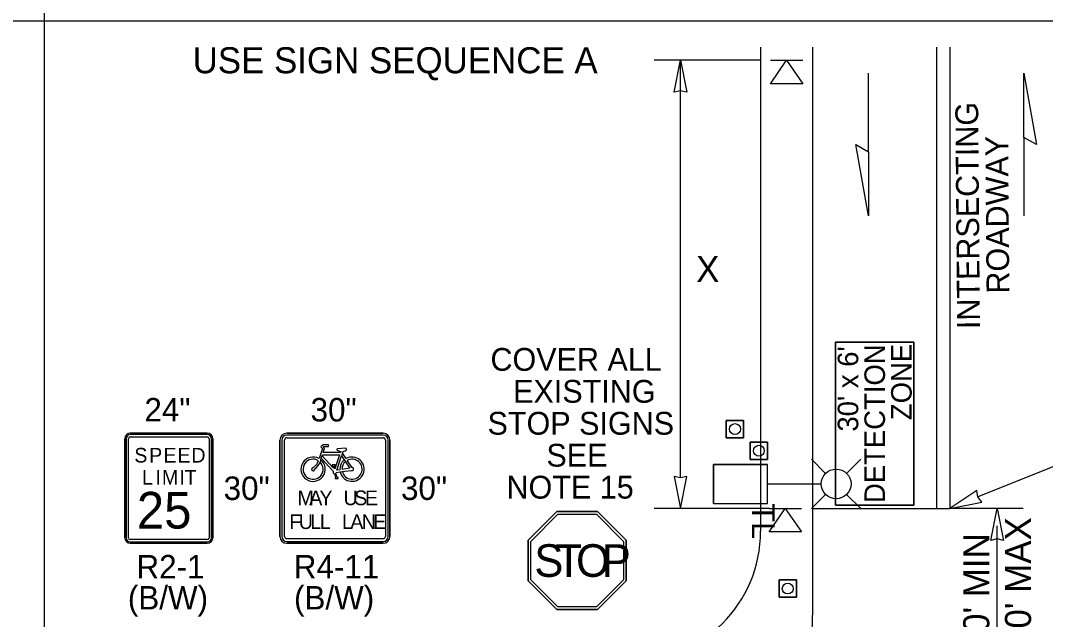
# Model space of a CAD drawing. Extents: x 99979.8 to 100075.7, y 99995 to 100010.7.
# Drawn here: x 100045.178 to 100048.321, y 100004.285 to 100006.122 of the extents above; entities that cross this region are included whole.
import ezdxf

# ---------------------------------------------------------------- set-up
doc = ezdxf.new("R2010")
doc.units = 0
for name, color, linetype in [('RD_ED_ShoulderPavedEdge', 7, 'Continuous'), ('RD_MK_LineDblYellowCenter', 7, 'Continuous'), ('RD_MK_LineEdgeWhite', 7, 'Continuous'), ('RD_MK_LineEdgeWhiteNew', 7, 'Continuous'), ('RD_MK_LineStop', 7, 'Continuous'), ('SH_DE_DetailBody1Text', 7, 'Continuous'), ('TR_SN_ConstructionSigns', 7, 'Continuous'), ('TR_WZ_PortableLightStandard', 7, 'Continuous'), ('TR_WZ_PortableSignMountBlk-Org', 7, 'Continuous'), ('TR_WZ_PortableSignMountBlk-Wht', 7, 'Continuous'), ('TR_WZ_TrafficCone', 7, 'Continuous'), ('TR_WZ_WorkZoneDetails', 7, 'Continuous'), ('TR_WZ_WorkZoneTextCurrent', 7, 'Continuous')]:
    doc.layers.add(name, color=color, linetype=linetype)

msp = doc.modelspace()

# ---------------------------------------------------------------- linework, layer by layer
at = {"layer": 'RD_ED_ShoulderPavedEdge'}
msp.add_lwpolyline([(100047.4475, 100006.0405), (100047.4475, 100004.5559)], dxfattribs=at)
msp.add_arc((100047.0475, 100004.5559), 0.4, 270, 0, dxfattribs=at)
at = {"layer": 'RD_MK_LineDblYellowCenter'}
for p, q in [((100047.9875, 100006.0405), (100047.9875, 100004.6259)), ((100048.0275, 100006.0405), (100048.0275, 100004.6259))]:
    msp.add_line(p, q, dxfattribs=at)
at = {"layer": 'RD_MK_LineEdgeWhite'}
for p, q in [((100047.6075, 100004.5559), (100047.6075, 100006.0405)), ((100047.6075, 100004.3159), (100047.6075, 100004.5559))]:
    msp.add_line(p, q, dxfattribs=at)
at = {"layer": 'RD_MK_LineEdgeWhiteNew'}
msp.add_arc((100046.1076, 100004.3239), 1.5, 277.2601, 359.6954, dxfattribs=at)
at = {"layer": 'RD_MK_LineStop'}
msp.add_line((100047.6075, 100004.6259), (100048.0275, 100004.6259), dxfattribs=at)
at = {"layer": 'TR_SN_ConstructionSigns'}
for p, q in [((100045.5142, 100004.8565), (100045.7505, 100004.8565)), ((100045.7505, 100004.8565), (100045.5142, 100004.8565)), ((100045.7505, 100004.8565), (100045.5142, 100004.8565)), ((100045.9944, 100004.8565), (100046.2897, 100004.8565)), ((100046.2897, 100004.8565), (100045.9944, 100004.8565)), ((100046.2897, 100004.8565), (100045.9944, 100004.8565)), ((100045.4973, 100004.5358), (100045.4973, 100004.8396)), ((100045.4973, 100004.8396), (100045.4973, 100004.5358)), ((100045.4973, 100004.8396), (100045.4973, 100004.5358)), ((100045.5016, 100004.8396), (100045.5016, 100004.5358)), ((100045.5086, 100004.5358), (100045.5086, 100004.8396)), ((100045.7505, 100004.8523), (100045.5142, 100004.8523)), ((100045.5142, 100004.8452), (100045.7505, 100004.8452)), ((100045.7561, 100004.8396), (100045.7561, 100004.5358)), ((100045.7631, 100004.5358), (100045.7631, 100004.8396)), ((100045.7673, 100004.8396), (100045.7673, 100004.5358)), ((100045.7673, 100004.5358), (100045.7673, 100004.8396)), ((100045.7673, 100004.5358), (100045.7673, 100004.8396)), ((100045.9733, 100004.5401), (100045.9733, 100004.8354)), ((100045.9733, 100004.8354), (100045.9733, 100004.5401)), ((100045.9733, 100004.8354), (100045.9733, 100004.5401)), ((100045.9789, 100004.8354), (100045.9789, 100004.5401)), ((100045.9873, 100004.5401), (100045.9873, 100004.8354)), ((100046.2897, 100004.8508), (100045.9944, 100004.8508)), ((100045.9944, 100004.8424), (100046.2897, 100004.8424)), ((100046.2967, 100004.8354), (100046.2967, 100004.5401)), ((100046.3051, 100004.5401), (100046.3051, 100004.8354)), ((100046.3108, 100004.8354), (100046.3108, 100004.5401)), ((100046.3108, 100004.5401), (100046.3108, 100004.8354)), ((100046.3108, 100004.5401), (100046.3108, 100004.8354)), ((100046.1037, 100004.8097), (100046.0933, 100004.7786)), ((100046.106, 100004.8213), (100046.0991, 100004.8143)), ((100046.0991, 100004.8143), (100046.1037, 100004.8097)), ((100046.1059, 100004.7972), (100046.1101, 100004.8097)), ((100046.1586, 100004.7972), (100046.1059, 100004.7972)), ((100046.1225, 100004.8213), (100046.106, 100004.8213)), ((100046.1061, 100004.8137), (100046.1083, 100004.8158)), ((100046.1101, 100004.8097), (100046.1061, 100004.8137)), ((100046.1083, 100004.8158), (100046.1225, 100004.8158)), ((100046.1225, 100004.8158), (100046.1225, 100004.8213)), ((100046.1744, 100004.8101), (100046.1495, 100004.8084)), ((100046.1597, 100004.8006), (100046.1586, 100004.7972)), ((100046.1647, 100004.7949), (100046.1621, 100004.787)), ((100046.1647, 100004.7949), (100046.1667, 100004.8007)), ((100046.1759, 100004.7784), (100046.1647, 100004.7949)), ((100046.0985, 100004.775), (100046.0963, 100004.7682)), ((100046.0985, 100004.775), (100046.1001, 100004.7797)), ((100046.1001, 100004.7797), (100046.1025, 100004.7868)), ((100046.1001, 100004.7797), (100046.1367, 100004.7399)), ((100046.1025, 100004.7868), (100046.1037, 100004.7906)), ((100046.1371, 100004.7492), (100046.1025, 100004.7868)), ((100046.1037, 100004.7906), (100046.1564, 100004.7906)), ((100046.1564, 100004.7906), (100046.1419, 100004.7473)), ((100046.1474, 100004.7428), (100046.1621, 100004.787)), ((100046.1621, 100004.787), (100046.1705, 100004.7746)), ((100046.1705, 100004.7746), (100046.1742, 100004.7691)), ((100046.1742, 100004.7691), (100046.188, 100004.7488)), ((100046.1945, 100004.751), (100046.1796, 100004.7729)), ((100046.1424, 100004.7599), (100046.1336, 100004.7599)), ((100046.1358, 100004.7566), (100046.1371, 100004.7492)), ((100046.1419, 100004.7473), (100046.1402, 100004.7566)), ((100046.1402, 100004.7566), (100046.1424, 100004.7566)), ((100046.141, 100004.7318), (100046.1446, 100004.721)), ((100046.1424, 100004.7566), (100046.1424, 100004.7599)), ((100046.1493, 100004.721), (100046.1452, 100004.7332)), ((100046.1469, 100004.7361), (100046.1582, 100004.7377)), ((100046.1573, 100004.7442), (100046.1474, 100004.7428)), ((100046.1582, 100004.7377), (100046.1647, 100004.7387)), ((100046.188, 100004.7488), (100046.1638, 100004.7452)), ((100046.1647, 100004.7387), (100046.191, 100004.7426)), ((100046.1446, 100004.721), (100046.1428, 100004.721)), ((100046.1428, 100004.721), (100046.1428, 100004.7177)), ((100046.1428, 100004.7177), (100046.1516, 100004.7177)), ((100046.1516, 100004.721), (100046.1493, 100004.721)), ((100046.1516, 100004.7177), (100046.1516, 100004.721)), ((100046.8229, 100004.6159), (100046.735, 100004.528)), ((100046.8229, 100004.6159), (100046.735, 100004.528)), ((100046.7428, 100004.5248), (100046.8261, 100004.6081)), ((100046.9472, 100004.6159), (100046.8229, 100004.6159)), ((100046.9472, 100004.6159), (100046.8229, 100004.6159)), ((100046.8261, 100004.6081), (100046.9439, 100004.6081)), ((100046.9439, 100004.6081), (100047.0272, 100004.5248)), ((100047.035, 100004.528), (100046.9472, 100004.6159)), ((100047.035, 100004.528), (100046.9472, 100004.6159)), ((100045.7505, 100004.5302), (100045.5142, 100004.5302)), ((100045.5142, 100004.5232), (100045.7505, 100004.5232)), ((100045.7505, 100004.519), (100045.5142, 100004.519)), ((100045.5142, 100004.519), (100045.7505, 100004.519)), ((100045.5142, 100004.519), (100045.7505, 100004.519)), ((100046.2897, 100004.533), (100045.9944, 100004.533)), ((100045.9944, 100004.5246), (100046.2897, 100004.5246)), ((100046.2897, 100004.519), (100045.9944, 100004.519)), ((100045.9944, 100004.519), (100046.2897, 100004.519)), ((100045.9944, 100004.519), (100046.2897, 100004.519)), ((100046.735, 100004.528), (100046.735, 100004.4038)), ((100046.735, 100004.528), (100046.735, 100004.4038)), ((100046.7428, 100004.407), (100046.7428, 100004.5248)), ((100047.0272, 100004.5248), (100047.0272, 100004.407)), ((100047.035, 100004.4038), (100047.035, 100004.528)), ((100047.035, 100004.4038), (100047.035, 100004.528)), ((100046.735, 100004.4038), (100046.8229, 100004.3159)), ((100046.735, 100004.4038), (100046.8229, 100004.3159)), ((100046.8261, 100004.3237), (100046.7428, 100004.407)), ((100047.0272, 100004.407), (100046.9439, 100004.3237)), ((100046.9472, 100004.3159), (100047.035, 100004.4038)), ((100046.9472, 100004.3159), (100047.035, 100004.4038)), ((100046.9439, 100004.3237), (100046.8261, 100004.3237)), ((100046.8229, 100004.3159), (100046.9472, 100004.3159)), ((100046.8229, 100004.3159), (100046.9472, 100004.3159))]:
    msp.add_line(p, q, dxfattribs=at)
for points in [[(100046.1336, 100004.7599), (100046.1336, 100004.7566), (100046.1358, 100004.7566)], [(100046.8229, 100004.6159), (100046.9472, 100004.6159), (100047.035, 100004.528), (100047.035, 100004.4038), (100046.9472, 100004.3159), (100046.8229, 100004.3159), (100046.735, 100004.4038), (100046.735, 100004.528), (100046.8229, 100004.6159)]]:
    msp.add_lwpolyline(points, dxfattribs=at)
for centre, radius, start, end in [((100045.5142, 100004.8396), 0.0169, 90, 180), ((100045.5142, 100004.8396), 0.0169, 90, 180), ((100045.5142, 100004.8396), 0.0169, 90, 180), ((100045.7505, 100004.8396), 0.0169, 0, 90), ((100045.7505, 100004.8396), 0.0169, 0, 90), ((100045.7505, 100004.8396), 0.0169, 0, 90), ((100045.9944, 100004.8354), 0.0211, 90, 180), ((100045.9944, 100004.8354), 0.0211, 90, 180), ((100045.9944, 100004.8354), 0.0211, 90, 180), ((100046.2897, 100004.8354), 0.0211, 0, 90), ((100046.2897, 100004.8354), 0.0211, 0, 90), ((100046.2897, 100004.8354), 0.0211, 0, 90), ((100045.5142, 100004.8396), 0.0127, 90, 180), ((100045.5142, 100004.8396), 0.00562, 90, 180), ((100045.7505, 100004.8396), 0.0127, 0, 90), ((100045.7505, 100004.8396), 0.00562, 0, 90), ((100045.9944, 100004.8354), 0.0155, 90, 180), ((100045.9944, 100004.8354), 0.00703, 90, 180), ((100046.2897, 100004.8354), 0.0155, 0, 90), ((100046.2897, 100004.8354), 0.00703, 0, 90), ((100046.1495, 100004.8062), 0.00219, 89.3854, 243.6828), ((100046.1747, 100004.8068), 0.00329, 294.5519, 96.4128), ((100046.075, 100004.7461), 0.0373, 60.5529, 50.868), ((100046.075, 100004.7461), 0.0307, 58.1532, 46.1649), ((100046.1945, 100004.7461), 0.0373, 130.0889, 182.8379), ((100046.1945, 100004.7461), 0.0373, 192.9622, 119.9648), ((100046.1945, 100004.7461), 0.0307, 131.3616, 181.6359), ((100046.1945, 100004.7461), 0.0307, 193.937, 119.0598), ((100046.075, 100004.7461), 0.00493, 105.257, 14.3233), ((100046.1415, 100004.7373), 0.00548, 151.1744, 264.8566), ((100046.1415, 100004.7373), 0.00548, 312.0053, 347.2932), ((100046.1945, 100004.7461), 0.00493, 225.1095, 90.4672), ((100045.5142, 100004.5358), 0.0169, 180, 270), ((100045.5142, 100004.5358), 0.0169, 180, 270), ((100045.5142, 100004.5358), 0.0169, 180, 270), ((100045.5142, 100004.5358), 0.0127, 180, 270), ((100045.5142, 100004.5358), 0.00562, 180, 270), ((100045.7505, 100004.5358), 0.0169, 270, 0), ((100045.7505, 100004.5358), 0.0169, 270, 0), ((100045.7505, 100004.5358), 0.0127, 270, 0), ((100045.7505, 100004.5358), 0.00562, 270, 0), ((100045.7505, 100004.5358), 0.0169, 270, 0), ((100045.9944, 100004.5401), 0.0211, 180, 270), ((100045.9944, 100004.5401), 0.0211, 180, 270), ((100045.9944, 100004.5401), 0.0211, 180, 270), ((100045.9944, 100004.5401), 0.0155, 180, 270), ((100045.9944, 100004.5401), 0.00703, 180, 270), ((100046.2897, 100004.5401), 0.0211, 270, 0), ((100046.2897, 100004.5401), 0.0211, 270, 0), ((100046.2897, 100004.5401), 0.0155, 270, 0), ((100046.2897, 100004.5401), 0.00703, 270, 0), ((100046.2897, 100004.5401), 0.0211, 270, 0)]:
    msp.add_arc(centre, radius, start, end, dxfattribs=at)
for centre, major_axis, ratio, start_param, end_param in [((100046.1627, 100004.8114), (-0.0186, 0), 0.588235, 0.686048, 1.410588), ((100046.1627, 100004.8114), (-0.0186, 0), 0.588235, 1.786993, 2.401245), ((100046.0799, 100004.7668), (-0.0105, -0.0158), 0.413554, 0.494612, 2.170849), ((100046.0799, 100004.7668), (-0.014, -0.021), 0.55814, 0.868091, 1.989998)]:
    msp.add_ellipse(centre, major_axis=major_axis, ratio=ratio, start_param=start_param, end_param=end_param, dxfattribs=at)
at = {"layer": 'TR_WZ_PortableLightStandard'}
for p, q in [((100047.303, 100004.7609), (100047.469, 100004.7609)), ((100047.303, 100004.6409), (100047.303, 100004.7609)), ((100047.469, 100004.7609), (100047.303, 100004.7609)), ((100047.469, 100004.6409), (100047.469, 100004.7609)), ((100047.6468, 100004.7333), (100047.6037, 100004.7764)), ((100047.7115, 100004.7333), (100047.7546, 100004.7764)), ((100047.469, 100004.7009), (100047.6334, 100004.7009)), ((100047.6468, 100004.6685), (100047.6037, 100004.6255)), ((100047.7115, 100004.6685), (100047.7546, 100004.6255)), ((100047.303, 100004.6409), (100047.469, 100004.6409)), ((100047.303, 100004.6409), (100047.469, 100004.6409))]:
    msp.add_line(p, q, dxfattribs=at)
for points in [[(100047.303, 100004.7609), (100047.303, 100004.7009), (100047.303, 100004.6409)], [(100047.469, 100004.6409), (100047.469, 100004.7009), (100047.469, 100004.7609)]]:
    msp.add_lwpolyline(points, dxfattribs=at)
msp.add_circle((100047.6792, 100004.7009), 0.0457, dxfattribs=at)
msp.add_circle((100047.6792, 100004.7009), 0.0457, dxfattribs=at)
at = {"layer": 'TR_WZ_PortableSignMountBlk-Org'}
msp.add_line((100047.4775, 100006.0004), (100047.5775, 100006.0004), dxfattribs=at)
msp.add_lwpolyline([(100047.5274, 100006.0004), (100047.5775, 100005.9286), (100047.4775, 100005.9286)], close=True, dxfattribs=at)
at = {"layer": 'TR_WZ_PortableSignMountBlk-Wht'}
msp.add_line((100047.4734, 100004.6259), (100047.5734, 100004.6259), dxfattribs=at)
msp.add_lwpolyline([(100047.5233, 100004.6259), (100047.5734, 100004.5541), (100047.4734, 100004.5541)], close=True, dxfattribs=at)
at = {"layer": 'TR_WZ_TrafficCone'}
for points in [[(100047.3956, 100004.8959), (100047.3956, 100004.8426), (100047.3423, 100004.8426), (100047.3423, 100004.8959), (100047.3956, 100004.8959)], [(100047.3423, 100004.8959), (100047.3423, 100004.8426), (100047.3956, 100004.8426), (100047.3956, 100004.8959), (100047.3423, 100004.8959)], [(100047.469, 100004.8292), (100047.469, 100004.7759), (100047.4156, 100004.7759), (100047.4156, 100004.8292), (100047.469, 100004.8292)], [(100047.4156, 100004.8292), (100047.4156, 100004.7759), (100047.469, 100004.7759), (100047.469, 100004.8292), (100047.4156, 100004.8292)], [(100047.5575, 100004.4066), (100047.5042, 100004.4066), (100047.5042, 100004.3533), (100047.5575, 100004.3533), (100047.5575, 100004.4066)], [(100047.5575, 100004.3533), (100047.5042, 100004.3533), (100047.5042, 100004.4066), (100047.5575, 100004.4066), (100047.5575, 100004.3533)]]:
    msp.add_lwpolyline(points, dxfattribs=at)
for centre in [(100047.369, 100004.8692), (100047.4423, 100004.8026), (100047.5308, 100004.38)]:
    msp.add_circle(centre, 0.0167, dxfattribs=at)
at = {"layer": 'TR_WZ_WorkZoneDetails'}
for p, q in [((100045.25, 100010.275), (100045.25, 100001.7859)), ((100045.25, 100006.1205), (100040, 100006.1205)), ((100050.5, 100006.1205), (100045.25, 100006.1205)), ((100047.4475, 100006.0004), (100047.1216, 100006.0004)), ((100047.2016, 100004.7196), (100047.2016, 100006.0004)), ((100047.778, 100005.7193), (100047.778, 100005.9604)), ((100048.2552, 100005.7639), (100048.2552, 100005.5228)), ((100048.5274, 100004.8267), (100048.1143, 100004.6614)), ((100046.735, 100004.528), (100046.8229, 100004.6159)), ((100046.8229, 100004.6159), (100046.735, 100004.528)), ((100046.8229, 100004.6159), (100046.8229, 100004.6159)), ((100046.8229, 100004.6159), (100046.9472, 100004.6159)), ((100046.9472, 100004.6159), (100046.8229, 100004.6159)), ((100046.9472, 100004.6159), (100047.035, 100004.528)), ((100047.035, 100004.528), (100046.9472, 100004.6159)), ((100047.4734, 100004.6259), (100047.1216, 100004.6259)), ((100048.253, 100004.6259), (100048.0275, 100004.6259)), ((100048.173, 100004.1596), (100048.173, 100004.5722)), ((100046.735, 100004.528), (100046.735, 100004.528)), ((100046.735, 100004.4038), (100046.735, 100004.528)), ((100046.735, 100004.528), (100046.735, 100004.4038)), ((100047.035, 100004.528), (100047.035, 100004.528)), ((100047.035, 100004.528), (100047.035, 100004.4038)), ((100047.035, 100004.4038), (100047.035, 100004.528)), ((100046.735, 100004.4038), (100046.735, 100004.4038)), ((100046.8229, 100004.3159), (100046.735, 100004.4038)), ((100046.735, 100004.4038), (100046.8229, 100004.3159)), ((100047.035, 100004.4038), (100046.9472, 100004.3159)), ((100046.9472, 100004.3159), (100047.035, 100004.4038)), ((100047.035, 100004.4038), (100047.035, 100004.4038)), ((100046.8229, 100004.3159), (100046.8229, 100004.3159)), ((100046.9472, 100004.3159), (100046.8229, 100004.3159)), ((100046.8229, 100004.3159), (100046.9472, 100004.3159)), ((100046.9472, 100004.3159), (100046.9472, 100004.3159))]:
    msp.add_line(p, q, dxfattribs=at)
for points in [[(100047.2016, 100006.0004), (100047.2208, 100005.9022), (100047.2016, 100005.9067), (100047.1823, 100005.9022)], [(100048.2552, 100005.9604), (100048.2938, 100005.7416), (100048.2552, 100005.7639)], [(100047.778, 100005.5228), (100047.7394, 100005.7416), (100047.778, 100005.7193)], [(100047.2016, 100004.6259), (100047.2208, 100004.7242), (100047.2016, 100004.7196), (100047.1823, 100004.7242)], [(100048.0275, 100004.6259), (100048.1258, 100004.6453), (100048.1143, 100004.6614), (100048.1112, 100004.681)], [(100048.173, 100004.6259), (100048.1923, 100004.5276), (100048.173, 100004.5322), (100048.1537, 100004.5276)]]:
    msp.add_lwpolyline(points, close=True, dxfattribs=at)
for points in [[(100047.6775, 100005.1359), (100047.6775, 100004.6359), (100047.9175, 100004.6359), (100047.9175, 100005.1359), (100047.6775, 100005.1359)], [(100047.9175, 100005.1359), (100047.9175, 100004.6359), (100047.6775, 100004.6359), (100047.6775, 100005.1359), (100047.9175, 100005.1359)]]:
    msp.add_lwpolyline(points, dxfattribs=at)

# ---------------------------------------------------------------- texts
at = {"layer": 'SH_DE_DetailBody1Text'}
for s, p in [('INTERSECTING', (100048.1204, 100005.176)), ('ROADWAY', (100048.2106, 100005.285))]:
    msp.add_text(s, height=0.07, rotation=90.4626, dxfattribs=at).set_placement(p)
at = {"layer": 'TR_SN_ConstructionSigns'}
for s, height, p in [('COVER ALL', 0.07, (100046.619, 100005.0479)), ('EXISTING', 0.07, (100046.6885, 100004.9499)), ('STOP SIGNS', 0.07, (100046.61, 100004.8519)), ('SEE', 0.07, (100046.7906, 100004.7539)), ('S', 0.045, (100045.5266, 100004.7665)), ('P', 0.045, (100045.572, 100004.7665)), ('E', 0.045, (100045.6161, 100004.7665)), ('E', 0.045, (100045.6589, 100004.7665)), ('D', 0.045, (100045.7016, 100004.7665)), ('L', 0.045, (100045.55, 100004.699)), ('I', 0.045, (100045.5914, 100004.699)), ('M', 0.045, (100045.6112, 100004.699)), ('I', 0.045, (100045.6652, 100004.699)), ('T', 0.045, (100045.6809, 100004.699)), ('NOTE 15', 0.07, (100046.6682, 100004.6559)), ('25', 0.1125, (100045.5345, 100004.564)), ('M', 0.045, (100046.027, 100004.6357)), ('A', 0.045, (100046.063, 100004.6357)), ('Y', 0.045, (100046.0945, 100004.6357)), ('U', 0.045, (100046.1683, 100004.6357)), ('S', 0.045, (100046.2012, 100004.6357)), ('E', 0.045, (100046.234, 100004.6357)), ('F', 0.045, (100046.0018, 100004.5626)), ('U', 0.045, (100046.0311, 100004.5626)), ('L', 0.045, (100046.0662, 100004.5626)), ('L', 0.045, (100046.0954, 100004.5626)), ('L', 0.045, (100046.1634, 100004.5626)), ('A', 0.045, (100046.189, 100004.5626)), ('N', 0.045, (100046.2241, 100004.5626)), ('E', 0.045, (100046.2592, 100004.5626))]:
    msp.add_text(s, height=height, dxfattribs=at).set_placement(p)
for s, p in [('24"', (100045.5576, 100004.8925)), ('30"', (100046.0673, 100004.8925)), ('30"', (100045.8006, 100004.6517)), ('30"', (100046.3446, 100004.6517)), ('R2-1', (100045.5332, 100004.411)), ('R4-11', (100046.0158, 100004.411)), ('(B/W)', (100045.5068, 100004.3159)), ('(B/W)', (100046.0165, 100004.3159))]:
    msp.add_text(s, height=0.072, rotation=360, dxfattribs=at).set_placement(p)
at = {"layer": 'TR_WZ_PortableLightStandard'}
msp.add_text('TL', height=0.07, rotation=270, dxfattribs=at).set_placement((100047.421, 100004.641))
at = {"layer": 'TR_WZ_WorkZoneDetails'}
for s, p in [("30' x 6'", (100047.7471, 100004.8614)), ('DETECTION', (100047.829, 100004.6423)), ('ZONE', (100047.9109, 100004.8966))]:
    msp.add_text(s, height=0.063, rotation=90, dxfattribs=at).set_placement(p)
for s, p in [('S', (100046.7535, 100004.4159)), ('T', (100046.8185, 100004.4159)), ('O', (100046.8815, 100004.4159)), ('P', (100046.9605, 100004.4159))]:
    msp.add_text(s, height=0.1, dxfattribs=at).set_placement(p)
at = {"layer": 'TR_WZ_WorkZoneTextCurrent'}
for s, p in [('USE SIGN SEQUENCE A', (100045.7054, 100005.9604)), ('X', (100047.2498, 100005.32))]:
    msp.add_text(s, height=0.08, dxfattribs=at).set_placement(p)
for s, p in [("100' MAX", (100048.277, 100004.1383)), ("40' MIN", (100048.149, 100004.1844))]:
    msp.add_text(s, height=0.08, rotation=90, dxfattribs=at).set_placement(p)

doc.saveas('drawing.dxf')
